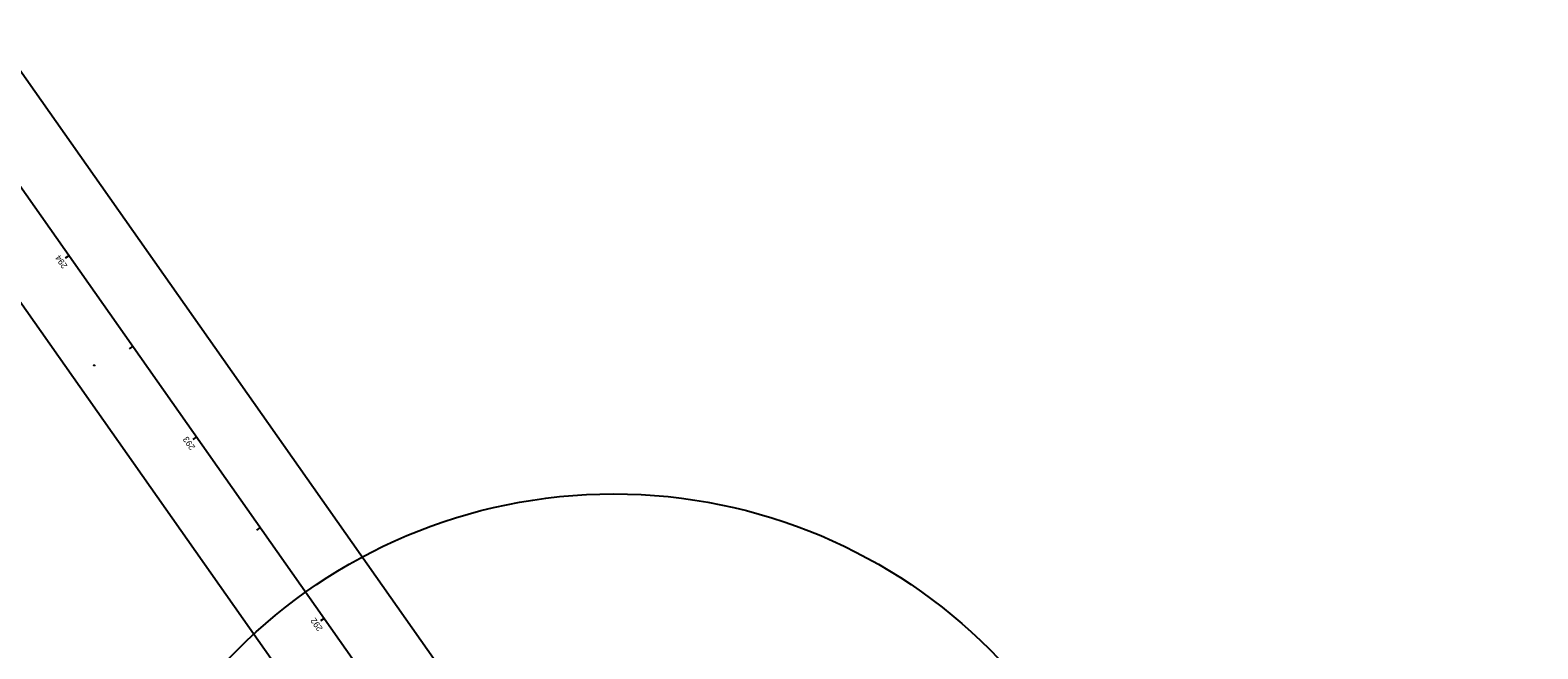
# Model space of a CAD drawing. Extents: x 1345023 to 1351589, y 535029 to 544731.
# Drawn here: x 1348802 to 1349481, y 539612 to 539891 of the extents above; entities that cross this region are included whole.
import ezdxf

# ---------------------------------------------------------------- set-up
doc = ezdxf.new("R2010")
doc.units = 0
for name, color, linetype in [('Default', 7, 'Continuous'), ('GE_X_CL_20', 7, 'Continuous'), ('RW_X_CL_20', 7, 'Continuous'), ('RW_X_Esmt_SH', 7, 'Continuous'), ('SV_P_Control_Cells_Set', 7, 'Continuous'), ('SV_X_Text_Elevation', 7, 'Continuous'), ('SV_X_Text_Name', 7, 'Continuous')]:
    doc.layers.add(name, color=color, linetype=linetype)

msp = doc.modelspace()

# ---------------------------------------------------------------- linework, layer by layer
at = {"layer": 'Default'}
msp.add_circle((1349064.59, 539442.56), 239.67, dxfattribs=at)
msp.add_circle((1349064.59, 539442.56), 239.67, dxfattribs=at)
at = {"layer": 'GE_X_CL_20'}
for p, q in [((1348819.01, 539789.68), (1348817.37, 539788.53)), ((1348847.77, 539748.78), (1348846.14, 539747.63)), ((1348876.54, 539707.89), (1348874.9, 539706.74)), ((1348905.3, 539666.99), (1348903.66, 539665.84)), ((1348934.06, 539626.09), (1348932.42, 539624.94))]:
    msp.add_line(p, q, dxfattribs=at)
at = {"layer": 'RW_X_CL_20'}
msp.add_line((1349456.54, 538883.15), (1348162.36, 540723.41), dxfattribs=at)
msp.add_line((1349456.54, 538883.15), (1348162.36, 540723.41), dxfattribs=at)
at = {"layer": 'RW_X_Esmt_SH'}
for p, q in [((1349481.08, 538900.4), (1348186.89, 540740.69)), ((1349432, 538865.89), (1348137.84, 540706.13))]:
    msp.add_line(p, q, dxfattribs=at)
at = {"layer": 'SV_P_Control_Cells_Set'}
for points in [[(1348830.36, 539740.15), (1348830.36, 539740.23), (1348830.39, 539740.15), (1348830.41, 539740.23), (1348830.41, 539740.15)], [(1348830.45, 539740.16), (1348830.45, 539740.16), (1348830.46, 539740.16), (1348830.46, 539740.15), (1348830.46, 539740.15), (1348830.46, 539740.15), (1348830.45, 539740.15), (1348830.45, 539740.15), (1348830.45, 539740.15), (1348830.45, 539740.15), (1348830.45, 539740.15), (1348830.45, 539740.16), (1348830.45, 539740.16)], [(1348830.48, 539740.15), (1348830.48, 539740.23), (1348830.52, 539740.15), (1348830.52, 539740.23)], [(1348830.56, 539740.16), (1348830.57, 539740.16), (1348830.57, 539740.16), (1348830.57, 539740.15), (1348830.57, 539740.15), (1348830.57, 539740.15), (1348830.57, 539740.15), (1348830.56, 539740.15), (1348830.56, 539740.15), (1348830.56, 539740.15), (1348830.56, 539740.15), (1348830.56, 539740.16), (1348830.56, 539740.16)], [(1348830.63, 539740.22), (1348830.63, 539740.22), (1348830.63, 539740.22), (1348830.62, 539740.23), (1348830.62, 539740.23), (1348830.61, 539740.23), (1348830.61, 539740.23), (1348830.6, 539740.23), (1348830.6, 539740.22), (1348830.59, 539740.22), (1348830.59, 539740.21), (1348830.59, 539740.21), (1348830.59, 539740.2), (1348830.6, 539740.2), (1348830.63, 539740.18), (1348830.63, 539740.18), (1348830.63, 539740.18), (1348830.63, 539740.17), (1348830.63, 539740.17), (1348830.63, 539740.16), (1348830.63, 539740.16), (1348830.63, 539740.16), (1348830.63, 539740.16), (1348830.63, 539740.15), (1348830.63, 539740.15), (1348830.63, 539740.15), (1348830.62, 539740.15), (1348830.62, 539740.15), (1348830.62, 539740.15), (1348830.61, 539740.15), (1348830.6, 539740.15), (1348830.6, 539740.15), (1348830.59, 539740.16)], [(1348830.67, 539740.16), (1348830.67, 539740.16), (1348830.68, 539740.16), (1348830.68, 539740.15), (1348830.68, 539740.15), (1348830.68, 539740.15), (1348830.67, 539740.15), (1348830.67, 539740.15), (1348830.67, 539740.15), (1348830.67, 539740.15), (1348830.67, 539740.15), (1348830.67, 539740.16), (1348830.67, 539740.16)]]:
    msp.add_lwpolyline(points, dxfattribs=at)
msp.add_circle((1348830.26, 539740.19), 0.0249, dxfattribs=at)

# ---------------------------------------------------------------- texts
at = {"layer": 'GE_X_CL_20'}
for s, p in [('294', (1348818.55, 539785.13)), ('293', (1348876.1, 539703.29)), ('292', (1348933.6, 539621.52))]:
    msp.add_text(s, height=2.8, rotation=125.11694, dxfattribs=at).set_placement(p)
at = {"layer": 'SV_X_Text_Elevation'}
msp.add_text('855.46', height=0.06, dxfattribs=at).set_placement((1348829.97, 539740.13))
at = {"layer": 'SV_X_Text_Name'}
msp.add_text('FV200', height=0.06, dxfattribs=at).set_placement((1348830, 539740.19))

doc.saveas('drawing.dxf')
